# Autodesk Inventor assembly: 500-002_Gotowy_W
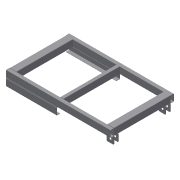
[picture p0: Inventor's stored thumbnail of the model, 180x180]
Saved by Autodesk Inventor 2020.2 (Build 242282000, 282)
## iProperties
Created: 2016-09
Part Number: 500-002_Gotowy_W
Document SubType Name: Assembly
Designer: F.Stasiak
Description: Stół
Manager: www.cadconsulting.pl
Company: Fabian Stasiak CAD Consulting
Author: F.Stasiak
Subject: Zbiór ćwiczeń. Autodesk Inventor 2020. Kurs podstawowy
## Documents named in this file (10)
- C:\2020_Kurs_podstawowy\R6 Zespoły\Warsztat\Komponenty\500-002_Gotowy_W.iam
- C:\2020_Kurs_podstawowy\R6 Zespoły\Warsztat\Komponenty\500-01-07.ipt
- C:\2020_Kurs_podstawowy\R6 Zespoły\Warsztat\Komponenty\500-01-06.ipt
- C:\2020_Kurs_podstawowy\R6 Zespoły\Warsztat\Komponenty\EN 10058 - 500-01-08.ipt
- C:\2020_Kurs_podstawowy\R6 Zespoły\Warsztat\Komponenty\DIN 120x60x4 500-01-01.ipt
- DIN 120x60x4 900-01-1.ipt
- C:\2020_Kurs_podstawowy\R6 Zespoły\Warsztat\Komponenty\DIN 120x60x4 500-01-04.ipt
- DIN 120x60x4 900-01-04.ipt
- C:\2020_Kurs_podstawowy\R6 Zespoły\Warsztat\Komponenty\DIN 120x60x4 500-01-02.ipt
- DIN 120x60x4 900-01-02.ipt
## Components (13 placed, 6 different names)
1. DIN 120x60x4 500-01-01:3 — Równoległy:21, Równoległy:23
2. DIN 120x60x4 500-01-01:4 — Zestawiający:18, Równoległy:22
3. DIN 120x60x4 500-01-04:3 — Zestawiający:17, Zestawiający:20, Zestawiający:21, Równoległy:24, Zestawiający:23, Zestawiający:24, Równoległy:25
4. DIN 120x60x4 500-01-04:4 — Zestawiający:16
5. DIN 120x60x4 500-01-02:2
6. 500-01-07:1 — Równoległy:22, Zestawiający:19, Zestawiający:21, Równoległy:24
7. 500-01-07:2 — Równoległy:23, Zestawiający:22, Zestawiający:24, Równoległy:25
8. 500-01-07:3 — Zestawiający:22, Zestawiający:23
9. 500-01-07:4 — Zestawiający:19, Zestawiający:20
10. 500-01-06:1
11. 500-01-06:2
12. EN 10058 - 500-01-08:1
13. EN 10058 - 500-01-08:2
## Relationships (14: Mate 9, Flush 5)
- Równoległy:21 [Flush]: DIN 120x60x4 500-01-01:3
- Zestawiający:16 [Mate]: DIN 120x60x4 500-01-04:4
- Zestawiający:17 [Mate]: DIN 120x60x4 500-01-04:3
- Zestawiający:18 [Mate]: DIN 120x60x4 500-01-01:4
- Równoległy:22 [Flush]: DIN 120x60x4 500-01-01:4 ↔ 500-01-07:1
- Równoległy:23 [Flush]: DIN 120x60x4 500-01-01:3 ↔ 500-01-07:2
- Zestawiający:19 [Mate]: 500-01-07:1 ↔ 500-01-07:4
- Zestawiający:20 [Mate]: DIN 120x60x4 500-01-04:3 ↔ 500-01-07:4
- Zestawiający:21 [Mate]: DIN 120x60x4 500-01-04:3 ↔ 500-01-07:1
- Równoległy:24 [Flush]: DIN 120x60x4 500-01-04:3 ↔ 500-01-07:1
- Zestawiający:22 [Mate]: 500-01-07:2 ↔ 500-01-07:3
- Zestawiający:23 [Mate]: DIN 120x60x4 500-01-04:3 ↔ 500-01-07:3
- Zestawiający:24 [Mate]: DIN 120x60x4 500-01-04:3 ↔ 500-01-07:2
- Równoległy:25 [Flush]: DIN 120x60x4 500-01-04:3 ↔ 500-01-07:2
